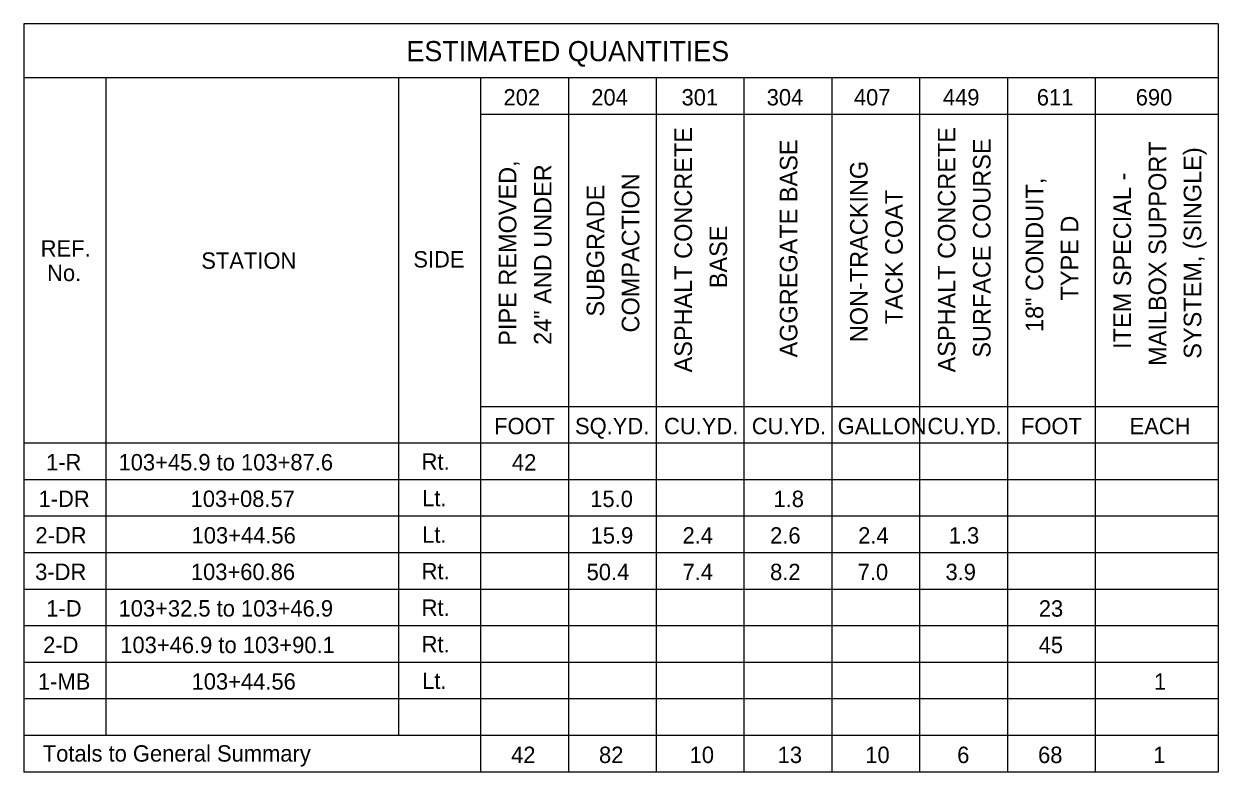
# Model space of a CAD drawing. Extents: x -44 to 74, y -34 to 24.
# Drawn here: x -2.9 to 7.3, y -26.91 to -20.52 of the extents above; entities that cross this region are included whole.
import ezdxf

# ---------------------------------------------------------------- set-up
doc = ezdxf.new("R2010")
doc.units = 0
doc.layers.add('GE_X_Alignment_100_Bearings', color=7, linetype='Continuous')
doc.layers.add('GE_X_Alignment_100_Curve_Data', color=7, linetype='Continuous')

msp = doc.modelspace()

# ---------------------------------------------------------------- linework, layer by layer
at = {"layer": 'GE_X_Alignment_100_Bearings'}
for p, q in [((-2.904, -20.516), (-2.904, -26.906)), ((7.296, -20.516), (-2.904, -20.516)), ((7.296, -20.516), (7.296, -26.906)), ((7.296, -20.978), (-2.904, -20.978)), ((-2.204, -20.978), (-2.204, -26.594)), ((0.296, -20.978), (0.296, -26.594)), ((0.996, -20.978), (0.996, -26.906)), ((1.746, -20.978), (1.746, -26.906)), ((2.496, -20.978), (2.496, -26.906)), ((3.246, -20.978), (3.246, -26.906)), ((3.996, -20.978), (3.996, -26.906)), ((4.746, -20.978), (4.746, -26.906)), ((5.496, -20.978), (5.496, -26.906)), ((6.246, -20.978), (6.246, -26.906)), ((7.296, -21.29), (0.996, -21.29)), ((7.296, -23.786), (0.996, -23.786)), ((7.296, -24.098), (-2.904, -24.098)), ((7.296, -24.41), (-2.904, -24.41)), ((7.296, -24.722), (-2.904, -24.722)), ((7.296, -25.034), (-2.904, -25.034)), ((7.296, -25.346), (-2.904, -25.346)), ((7.296, -25.658), (-2.904, -25.658)), ((7.296, -25.97), (-2.904, -25.97)), ((7.296, -26.282), (-2.904, -26.282)), ((7.296, -26.594), (-2.904, -26.594)), ((7.296, -26.906), (-2.904, -26.906))]:
    msp.add_line(p, q, dxfattribs=at)

# ---------------------------------------------------------------- texts
msp.add_text('ESTIMATED QUANTITIES', height=0.17175, dxfattribs=at).set_placement((0.363, -20.835))
at = {"layer": 'GE_X_Alignment_100_Curve_Data'}
for s, p in [('202', (1.192, -21.213)), ('204', (1.942, -21.213)), ('301', (2.713, -21.213)), ('304', (3.44, -21.213)), ('407', (4.185, -21.213)), ('449', (4.945, -21.213)), ('611', (5.747, -21.213)), ('690', (6.592, -21.213)), ('REF.', (-2.761, -22.504)), ('STATION', (-1.389, -22.608)), ('SIDE', (0.422, -22.597)), ('No.', (-2.706, -22.713)), ('FOOT', (1.112, -24.021)), ('SQ.YD.', (1.803, -24.021)), ('CU.YD.', (2.563, -24.021)), ('CU.YD.', (3.313, -24.021)), ('GALLON', (4.046, -24.021)), ('CU.YD.', (4.813, -24.021)), ('FOOT', (5.612, -24.021)), ('EACH', (6.54, -24.021)), ('1-R', (-2.715, -24.33)), ('103+45.9 to 103+87.6', (-2.096, -24.33)), ('Rt.', (0.493, -24.324)), ('42', (1.264, -24.331)), ('1-DR', (-2.779, -24.642)), ('103+08.57', (-1.48, -24.642)), ('Lt.', (0.497, -24.636)), ('15.0', (1.933, -24.643)), ('1.8', (3.498, -24.643)), ('2-DR', (-2.806, -24.954)), ('103+44.56', (-1.472, -24.954)), ('Lt.', (0.497, -24.948)), ('15.9', (1.936, -24.955)), ('2.4', (2.721, -24.955)), ('2.6', (3.469, -24.955)), ('2.4', (4.221, -24.955)), ('1.3', (4.995, -24.955)), ('3-DR', (-2.808, -25.266)), ('103+60.86', (-1.478, -25.266)), ('Rt.', (0.493, -25.26)), ('50.4', (1.902, -25.267)), ('7.4', (2.721, -25.267)), ('8.2', (3.469, -25.267)), ('7.0', (4.217, -25.267)), ('3.9', (4.967, -25.267)), ('1-D', (-2.713, -25.578)), ('103+32.5 to 103+46.9', (-2.096, -25.578)), ('Rt.', (0.493, -25.572)), ('23', (5.764, -25.579)), ('2-D', (-2.74, -25.89)), ('103+46.9 to 103+90.1', (-2.081, -25.89)), ('Rt.', (0.493, -25.884)), ('45', (5.763, -25.891)), ('1-MB', (-2.784, -26.202)), ('103+44.56', (-1.472, -26.202)), ('Lt.', (0.497, -26.196)), ('1', (6.748, -26.203)), ('Totals to General Summary', (-2.743, -26.817)), ('42', (1.257, -26.829)), ('82', (2.008, -26.829)), ('10', (2.782, -26.829)), ('13', (3.534, -26.829)), ('10', (4.282, -26.829)), ('6', (5.067, -26.829)), ('68', (5.758, -26.829)), ('1', (6.742, -26.829))]:
    msp.add_text(s, height=0.14, dxfattribs=at).set_placement(p)
for s, p in [('ASPHALT CONCRETE', (2.802, -23.493)), ('ASPHALT CONCRETE', (5.052, -23.493)), ('AGGREGATE BASE', (3.702, -23.365)), ('SURFACE COURSE', (5.352, -23.367)), ('MAILBOX SUPPORT', (6.852, -23.437)), ('SYSTEM, (SINGLE)', (7.152, -23.376)), ('PIPE REMOVED,', (1.302, -23.265)), ('24" AND UNDER', (1.602, -23.258)), ('NON-TRACKING', (4.302, -23.235)), ('COMPACTION', (2.352, -23.152)), ('ITEM SPECIAL -', (6.552, -23.292)), ('SUBGRADE', (2.052, -23.016)), ('18" CONDUIT,', (5.802, -23.148)), ('TACK COAT', (4.602, -23.081)), ('TYPE D', (6.102, -22.879)), ('BASE', (3.102, -22.774))]:
    msp.add_text(s, height=0.15, rotation=90, dxfattribs=at).set_placement(p)

doc.saveas('drawing.dxf')
